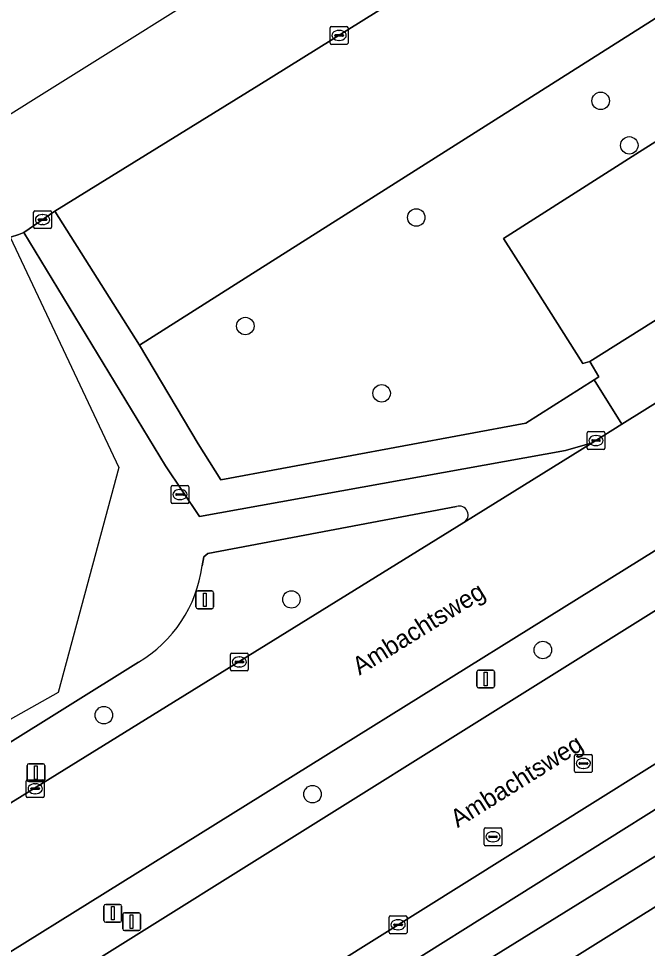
# Model space of a CAD drawing. Extents: x 158455 to 159797, y 387218 to 388672.
# Drawn here: x 158486.5 to 158521.8, y 387842.6 to 387894.7 of the extents above; entities that cross this region are included whole.
import ezdxf

# ---------------------------------------------------------------- set-up
doc = ezdxf.new("R2010")
doc.units = 0
for name, color, linetype in [('IMGEO_Berm_groen', 7, 'Continuous'), ('IMGEO_Boom', 7, 'Continuous'), ('IMGEO_Erf', 7, 'Continuous'), ('IMGEO_Fietspad_open', 7, 'Continuous'), ('IMGEO_Groenvoorziening', 7, 'Continuous'), ('IMGEO_Kolk', 7, 'Continuous'), ('IMGEO_Lichtmast', 7, 'Continuous'), ('IMGEO_Openbare_ruimte_label', 7, 'Continuous'), ('IMGEO_Pand', 7, 'Continuous'), ('IMGEO_Rijbaan_lokaal_gesloten', 7, 'Continuous'), ('IMGEO_Rijbaan_lokaal_open', 7, 'Continuous'), ('IMGEO_Rioolput', 7, 'Continuous'), ('IMGEO_Verkeersbordpaal', 7, 'Continuous'), ('IMGEO_Voetpad_open', 7, 'Continuous')]:
    doc.layers.add(name, color=color, linetype=linetype)

msp = doc.modelspace()

# ---------------------------------------------------------------- linework, layer by layer
at = {"layer": 'IMGEO_Berm_groen'}
for points in [[(158511.066, 387867.368), (158497.138, 387864.732), (158496.915, 387864.542), (158496.826, 387864.039)], [(158475.023, 387843.917), (158511.48, 387866.466)], [(158522.28, 387864.951), (158479.024, 387838.051)], [(158480.509, 387835.487), (158523.75, 387862.509)], [(158493.253, 387858.646), (158473.66, 387846.433)]]:
    msp.add_lwpolyline(points, dxfattribs=at)
for centre, radius, start, end in [((158511.214, 387866.89), 0.5, 302.0715, 107.2369), ((158489.463, 387865.037), 7.431, 300.6705, 352.2785)]:
    msp.add_arc(centre, radius, start, end, dxfattribs=at)
at = {"layer": 'IMGEO_Boom'}
for centre in [(158519.135, 387890.071), (158520.738, 387887.579), (158508.811, 387883.542), (158499.24, 387877.465), (158506.872, 387873.699), (158501.823, 387862.161), (158515.9, 387859.331), (158491.32, 387855.679), (158503.005, 387851.257)]:
    msp.add_circle(centre, 0.489, dxfattribs=at)
at = {"layer": 'IMGEO_Erf'}
msp.add_lwpolyline([(158535.835, 387896.338), (158532.941, 387894.608), (158530.053, 387892.77), (158527.156, 387890.928), (158524.238, 387889.072), (158521.319, 387887.219), (158513.704, 387882.37), (158514.815, 387880.615), (158518.14, 387875.366), (158518.531, 387875.474), (158524.198, 387879.051), (158524.955, 387877.885), (158538.307, 387886.237)], dxfattribs=at)
at = {"layer": 'IMGEO_Fietspad_open'}
for points in [[(158511.48, 387866.466), (158518.654, 387870.921), (158517.16, 387870.5), (158496.679, 387866.801), (158494.767, 387869.64), (158486.831, 387882.706), (158486.558, 387882.594), (158486.101, 387882.446), (158486.082, 387882.442), (158486.082, 387882.442), (158492.168, 387869.555), (158488.76, 387856.956), (158471.29, 387847.126)], [(158496.826, 387864.039), (158496.915, 387864.542), (158497.138, 387864.732), (158511.066, 387867.368)], [(158471.29, 387847.126), (158472.279, 387845.559), (158473.66, 387846.433), (158493.253, 387858.646)]]:
    msp.add_lwpolyline(points, dxfattribs=at)
for centre, radius, start, end in [((158511.214, 387866.89), 0.5, 302.0715, 107.2369), ((158489.463, 387865.037), 7.431, 300.6705, 352.2785)]:
    msp.add_arc(centre, radius, start, end, dxfattribs=at)
at = {"layer": 'IMGEO_Groenvoorziening'}
msp.add_lwpolyline([(158488.574, 387883.891), (158493.308, 387876.386), (158500, 387880.63), (158536.681, 387903.888), (158589.704, 387936.796), (158585.207, 387943.981), (158555.076, 387925.231), (158500, 387890.959)], close=True, dxfattribs=at)
msp.add_lwpolyline([(158536.681, 387903.888), (158500, 387880.63), (158493.308, 387876.386), (158496.607, 387870.873), (158497.879, 387868.851), (158514.948, 387872.022), (158518.78, 387874.449), (158519.038, 387874.618), (158518.531, 387875.474), (158518.14, 387875.366), (158514.815, 387880.615), (158513.704, 387882.37), (158521.319, 387887.219), (158524.238, 387889.072), (158527.156, 387890.928), (158530.053, 387892.77), (158532.941, 387894.608), (158535.835, 387896.338)], dxfattribs=at)
at = {"layer": 'IMGEO_Kolk'}
for p, q in [((158503.991, 387893.31), (158503.991, 387894.162)), ((158504.066, 387894.236), (158504.918, 387894.236)), ((158504.479, 387894.016), (158504.504, 387894.016)), ((158504.992, 387894.162), (158504.992, 387893.31)), ((158504.25, 387893.73), (158504.25, 387893.742)), ((158504.688, 387893.693), (158504.29, 387893.693)), ((158504.293, 387893.779), (158504.691, 387893.779)), ((158504.502, 387893.456), (158504.477, 387893.456)), ((158504.734, 387893.742), (158504.734, 387893.73)), ((158504.918, 387893.236), (158504.066, 387893.236)), ((158487.387, 387882.997), (158487.387, 387883.849)), ((158487.462, 387883.923), (158488.314, 387883.923)), ((158487.646, 387883.417), (158487.646, 387883.429)), ((158487.689, 387883.466), (158488.087, 387883.466)), ((158487.875, 387883.703), (158487.9, 387883.703)), ((158488.13, 387883.429), (158488.13, 387883.417)), ((158488.388, 387883.849), (158488.388, 387882.997)), ((158488.314, 387882.923), (158487.462, 387882.923)), ((158488.084, 387883.38), (158487.686, 387883.38)), ((158487.898, 387883.143), (158487.873, 387883.143)), ((158518.374, 387870.629), (158518.374, 387871.481)), ((158518.449, 387871.555), (158519.301, 387871.555)), ((158519.375, 387871.481), (158519.375, 387870.629)), ((158518.633, 387871.049), (158518.633, 387871.061)), ((158519.071, 387871.012), (158518.673, 387871.012)), ((158518.676, 387871.098), (158519.074, 387871.098)), ((158518.862, 387871.335), (158518.887, 387871.335)), ((158519.117, 387871.061), (158519.117, 387871.049)), ((158519.301, 387870.555), (158518.449, 387870.555)), ((158518.885, 387870.775), (158518.86, 387870.775)), ((158495.083, 387867.606), (158495.083, 387868.458)), ((158495.158, 387868.532), (158496.01, 387868.532)), ((158495.571, 387868.312), (158495.596, 387868.312)), ((158496.084, 387868.458), (158496.084, 387867.606)), ((158495.342, 387868.026), (158495.342, 387868.038)), ((158495.78, 387867.989), (158495.382, 387867.989)), ((158495.385, 387868.075), (158495.783, 387868.075)), ((158495.826, 387868.038), (158495.826, 387868.026)), ((158496.01, 387867.532), (158495.158, 387867.532)), ((158495.594, 387867.752), (158495.569, 387867.752)), ((158498.408, 387858.233), (158498.408, 387859.085)), ((158498.483, 387859.159), (158499.335, 387859.159)), ((158499.409, 387859.085), (158499.409, 387858.233)), ((158498.667, 387858.653), (158498.667, 387858.665)), ((158499.105, 387858.616), (158498.707, 387858.616)), ((158498.71, 387858.702), (158499.108, 387858.702)), ((158498.896, 387858.939), (158498.921, 387858.939)), ((158499.151, 387858.665), (158499.151, 387858.653)), ((158499.335, 387858.159), (158498.483, 387858.159)), ((158498.919, 387858.379), (158498.894, 387858.379)), ((158486.975, 387851.139), (158486.975, 387851.991)), ((158487.05, 387852.065), (158487.902, 387852.065)), ((158487.463, 387851.845), (158487.488, 387851.845)), ((158487.976, 387851.991), (158487.976, 387851.139)), ((158487.234, 387851.559), (158487.234, 387851.571)), ((158487.672, 387851.522), (158487.274, 387851.522)), ((158487.277, 387851.608), (158487.675, 387851.608)), ((158487.486, 387851.285), (158487.461, 387851.285)), ((158487.718, 387851.571), (158487.718, 387851.559)), ((158487.902, 387851.065), (158487.05, 387851.065)), ((158507.294, 387843.521), (158507.294, 387844.373)), ((158507.369, 387844.447), (158508.221, 387844.447)), ((158508.295, 387844.373), (158508.295, 387843.521)), ((158507.553, 387843.941), (158507.553, 387843.953)), ((158507.991, 387843.904), (158507.593, 387843.904)), ((158507.596, 387843.99), (158507.994, 387843.99)), ((158507.782, 387844.227), (158507.807, 387844.227)), ((158508.037, 387843.953), (158508.037, 387843.941)), ((158508.221, 387843.447), (158507.369, 387843.447)), ((158507.805, 387843.667), (158507.78, 387843.667))]:
    msp.add_line(p, q, dxfattribs=at)
for points in [[(158503.991, 387893.31), (158503.991, 387894.162)], [(158504.066, 387894.236), (158504.918, 387894.236)], [(158504.992, 387894.162), (158504.992, 387893.31)], [(158504.918, 387893.236), (158504.066, 387893.236)], [(158487.387, 387882.997), (158487.387, 387883.849)], [(158487.462, 387883.923), (158488.314, 387883.923)], [(158488.388, 387883.849), (158488.388, 387882.997)], [(158488.314, 387882.923), (158487.462, 387882.923)], [(158518.374, 387870.629), (158518.374, 387871.481)], [(158518.449, 387871.555), (158519.301, 387871.555)], [(158519.375, 387871.481), (158519.375, 387870.629)], [(158519.301, 387870.555), (158518.449, 387870.555)], [(158495.083, 387867.606), (158495.083, 387868.458)], [(158495.158, 387868.532), (158496.01, 387868.532)], [(158496.084, 387868.458), (158496.084, 387867.606)], [(158496.01, 387867.532), (158495.158, 387867.532)], [(158498.408, 387858.233), (158498.408, 387859.085)], [(158498.483, 387859.159), (158499.335, 387859.159)], [(158499.409, 387859.085), (158499.409, 387858.233)], [(158499.335, 387858.159), (158498.483, 387858.159)], [(158486.975, 387851.139), (158486.975, 387851.991)], [(158487.05, 387852.065), (158487.902, 387852.065)], [(158487.976, 387851.991), (158487.976, 387851.139)], [(158487.902, 387851.065), (158487.05, 387851.065)], [(158507.294, 387843.521), (158507.294, 387844.373)], [(158507.369, 387844.447), (158508.221, 387844.447)], [(158508.295, 387844.373), (158508.295, 387843.521)], [(158508.221, 387843.447), (158507.369, 387843.447)]]:
    msp.add_lwpolyline(points, dxfattribs=at)
for centre, radius, start, end in [((158504.068, 387894.16), 0.0765, 91.552, 178.448), ((158504.068, 387894.16), 0.0765, 91.552, 178.448), ((158504.916, 387894.16), 0.0765, 1.552, 88.448), ((158504.916, 387894.16), 0.0765, 1.552, 88.448), ((158504.068, 387893.312), 0.0765, 181.552, 268.448), ((158504.068, 387893.312), 0.0765, 181.552, 268.448), ((158504.29, 387893.739), 0.0403, 85.8775, 175.7526), ((158504.287, 387893.729), 0.0366, 178.938, 274.7102), ((158504.691, 387893.736), 0.043, 264.8664, 352.4533), ((158504.695, 387893.741), 0.0386, 1.7309, 96.639), ((158504.916, 387893.312), 0.0765, 271.552, 358.448), ((158504.916, 387893.312), 0.0765, 271.552, 358.448), ((158487.464, 387883.847), 0.0765, 91.552, 178.448), ((158487.464, 387883.847), 0.0765, 91.552, 178.448), ((158487.686, 387883.426), 0.0403, 85.8775, 175.7526), ((158487.683, 387883.416), 0.0366, 178.938, 274.7102), ((158488.087, 387883.423), 0.043, 264.8664, 352.4533), ((158488.091, 387883.428), 0.0386, 1.7309, 96.639), ((158488.312, 387883.847), 0.0765, 1.552, 88.448), ((158488.312, 387883.847), 0.0765, 1.552, 88.448), ((158487.464, 387882.999), 0.0765, 181.552, 268.448), ((158487.464, 387882.999), 0.0765, 181.552, 268.448), ((158488.312, 387882.999), 0.0765, 271.552, 358.448), ((158488.312, 387882.999), 0.0765, 271.552, 358.448), ((158518.451, 387871.479), 0.0765, 91.552, 178.448), ((158518.451, 387871.479), 0.0765, 91.552, 178.448), ((158519.299, 387871.479), 0.0765, 1.552, 88.448), ((158519.299, 387871.479), 0.0765, 1.552, 88.448), ((158518.673, 387871.058), 0.0403, 85.8775, 175.7526), ((158518.67, 387871.048), 0.0366, 178.938, 274.7102), ((158519.074, 387871.055), 0.043, 264.8664, 352.4533), ((158519.078, 387871.06), 0.0386, 1.7309, 96.639), ((158518.451, 387870.631), 0.0765, 181.552, 268.448), ((158518.451, 387870.631), 0.0765, 181.552, 268.448), ((158519.299, 387870.631), 0.0765, 271.552, 358.448), ((158519.299, 387870.631), 0.0765, 271.552, 358.448), ((158495.16, 387868.456), 0.0765, 91.552, 178.448), ((158495.16, 387868.456), 0.0765, 91.552, 178.448), ((158496.008, 387868.456), 0.0765, 1.552, 88.448), ((158496.008, 387868.456), 0.0765, 1.552, 88.448), ((158495.382, 387868.035), 0.0403, 85.8775, 175.7526), ((158495.379, 387868.025), 0.0366, 178.938, 274.7102), ((158495.783, 387868.032), 0.043, 264.8664, 352.4533), ((158495.787, 387868.037), 0.0386, 1.7309, 96.639), ((158495.16, 387867.608), 0.0765, 181.552, 268.448), ((158495.16, 387867.608), 0.0765, 181.552, 268.448), ((158496.008, 387867.608), 0.0765, 271.552, 358.448), ((158496.008, 387867.608), 0.0765, 271.552, 358.448), ((158498.485, 387859.083), 0.0765, 91.552, 178.448), ((158498.485, 387859.083), 0.0765, 91.552, 178.448), ((158499.333, 387859.083), 0.0765, 1.552, 88.448), ((158499.333, 387859.083), 0.0765, 1.552, 88.448), ((158498.707, 387858.662), 0.0403, 85.8775, 175.7526), ((158498.704, 387858.652), 0.0366, 178.938, 274.7102), ((158499.108, 387858.659), 0.043, 264.8664, 352.4533), ((158499.112, 387858.664), 0.0386, 1.7309, 96.639), ((158498.485, 387858.235), 0.0765, 181.552, 268.448), ((158498.485, 387858.235), 0.0765, 181.552, 268.448), ((158499.333, 387858.235), 0.0765, 271.552, 358.448), ((158499.333, 387858.235), 0.0765, 271.552, 358.448), ((158487.052, 387851.989), 0.0765, 91.552, 178.448), ((158487.052, 387851.989), 0.0765, 91.552, 178.448), ((158487.9, 387851.989), 0.0765, 1.552, 88.448), ((158487.9, 387851.989), 0.0765, 1.552, 88.448), ((158487.052, 387851.141), 0.0765, 181.552, 268.448), ((158487.052, 387851.141), 0.0765, 181.552, 268.448), ((158487.274, 387851.568), 0.0403, 85.8775, 175.7526), ((158487.271, 387851.558), 0.0366, 178.938, 274.7102), ((158487.675, 387851.565), 0.043, 264.8664, 352.4533), ((158487.679, 387851.57), 0.0386, 1.7309, 96.639), ((158487.9, 387851.141), 0.0765, 271.552, 358.448), ((158487.9, 387851.141), 0.0765, 271.552, 358.448), ((158507.371, 387844.371), 0.0765, 91.552, 178.448), ((158507.371, 387844.371), 0.0765, 91.552, 178.448), ((158508.219, 387844.371), 0.0765, 1.552, 88.448), ((158508.219, 387844.371), 0.0765, 1.552, 88.448), ((158507.593, 387843.95), 0.0403, 85.8775, 175.7526), ((158507.59, 387843.94), 0.0366, 178.938, 274.7102), ((158507.994, 387843.947), 0.043, 264.8664, 352.4533), ((158507.998, 387843.952), 0.0386, 1.7309, 96.639), ((158507.371, 387843.523), 0.0765, 181.552, 268.448), ((158507.371, 387843.523), 0.0765, 181.552, 268.448), ((158508.219, 387843.523), 0.0765, 271.552, 358.448), ((158508.219, 387843.523), 0.0765, 271.552, 358.448)]:
    msp.add_arc(centre, radius, start, end, dxfattribs=at)
for centre, major_axis, ratio, start_param, end_param in [((158504.478, 387893.736), (-0.387, 0.002), 0.722429, 4.712389, 7.853982), ((158504.503, 387893.736), (-0.39, 0.002), 0.717154, 1.570796, 4.712389), ((158487.874, 387883.423), (-0.387, 0.002), 0.722429, 4.712389, 7.853982), ((158487.899, 387883.423), (-0.39, 0.002), 0.717154, 1.570796, 4.712389), ((158518.861, 387871.055), (-0.387, 0.002), 0.722429, 4.712389, 7.853982), ((158518.886, 387871.055), (-0.39, 0.002), 0.717154, 1.570796, 4.712389), ((158495.57, 387868.032), (-0.387, 0.002), 0.722429, 4.712389, 7.853982), ((158495.595, 387868.032), (-0.39, 0.002), 0.717154, 1.570796, 4.712389), ((158498.895, 387858.659), (-0.387, 0.002), 0.722429, 4.712389, 7.853982), ((158498.92, 387858.659), (-0.39, 0.002), 0.717154, 1.570796, 4.712389), ((158487.462, 387851.565), (-0.387, 0.002), 0.722429, 4.712389, 7.853982), ((158487.487, 387851.565), (-0.39, 0.002), 0.717154, 1.570796, 4.712389), ((158507.781, 387843.947), (-0.387, 0.002), 0.722429, 4.712389, 7.853982), ((158507.806, 387843.947), (-0.39, 0.002), 0.717154, 1.570796, 4.712389)]:
    msp.add_ellipse(centre, major_axis=major_axis, ratio=ratio, start_param=start_param, end_param=end_param, dxfattribs=at)
at = {"layer": 'IMGEO_Lichtmast'}
for p, q in [((158496.574, 387862.638), (158497.364, 387862.638)), ((158497.364, 387862.638), (158496.574, 387862.638)), ((158496.474, 387861.738), (158496.474, 387862.538)), ((158496.474, 387862.538), (158496.474, 387861.738)), ((158497.464, 387862.538), (158497.464, 387861.738)), ((158497.464, 387861.738), (158497.464, 387862.538)), ((158497.364, 387861.638), (158496.574, 387861.638)), ((158496.574, 387861.638), (158497.364, 387861.638)), ((158512.203, 387857.307), (158512.203, 387858.107)), ((158512.203, 387858.107), (158512.203, 387857.307)), ((158512.303, 387858.207), (158513.093, 387858.207)), ((158513.093, 387858.207), (158512.303, 387858.207)), ((158513.193, 387858.107), (158513.193, 387857.307)), ((158513.193, 387857.307), (158513.193, 387858.107)), ((158513.093, 387857.207), (158512.303, 387857.207)), ((158512.303, 387857.207), (158513.093, 387857.207)), ((158491.323, 387844.19), (158491.323, 387844.99)), ((158491.323, 387844.99), (158491.323, 387844.19)), ((158491.423, 387845.09), (158492.213, 387845.09)), ((158492.213, 387845.09), (158491.423, 387845.09)), ((158492.313, 387844.99), (158492.313, 387844.19)), ((158492.313, 387844.19), (158492.313, 387844.99)), ((158492.213, 387844.09), (158491.423, 387844.09)), ((158491.423, 387844.09), (158492.213, 387844.09))]:
    msp.add_line(p, q, dxfattribs=at)
for points in [[(158496.894, 387862.513), (158497.044, 387862.513), (158497.044, 387861.763), (158496.894, 387861.763), (158496.894, 387862.513)], [(158512.623, 387858.082), (158512.773, 387858.082), (158512.773, 387857.332), (158512.623, 387857.332), (158512.623, 387858.082)], [(158491.743, 387844.965), (158491.893, 387844.965), (158491.893, 387844.215), (158491.743, 387844.215), (158491.743, 387844.965)]]:
    msp.add_lwpolyline(points, dxfattribs=at)
for centre, start, end in [((158496.574, 387862.538), 90, 180), ((158496.574, 387862.538), 90, 180), ((158497.364, 387862.538), 0, 90), ((158497.364, 387862.538), 360, 90), ((158496.574, 387861.738), 180, 270), ((158496.574, 387861.738), 180, 270), ((158497.364, 387861.738), 270, 0), ((158497.364, 387861.738), 270, 0), ((158512.303, 387858.107), 90, 180), ((158512.303, 387858.107), 90, 180), ((158513.093, 387858.107), 0, 90), ((158513.093, 387858.107), 360, 90), ((158512.303, 387857.307), 180, 270), ((158512.303, 387857.307), 180, 270), ((158513.093, 387857.307), 270, 0), ((158513.093, 387857.307), 270, 0), ((158491.423, 387844.99), 90, 180), ((158491.423, 387844.99), 90, 180), ((158492.213, 387844.99), 0, 90), ((158492.213, 387844.99), 360, 90), ((158491.423, 387844.19), 180, 270), ((158491.423, 387844.19), 180, 270), ((158492.213, 387844.19), 270, 0), ((158492.213, 387844.19), 270, 0)]:
    msp.add_arc(centre, 0.1, start, end, dxfattribs=at)
at = {"layer": 'IMGEO_Pand'}
msp.add_lwpolyline([(158590.88, 387815.701), (158566.375, 387854.935), (158566.298, 387855.058), (158558.463, 387867.603), (158533.202, 387851.826), (158531.124, 387850.528), (158499.908, 387831.032), (158500, 387830.885), (158507.802, 387818.394), (158509.51, 387815.659), (158509.563, 387815.483), (158512.249, 387806.568), (158519.071, 387800.209), (158520.945, 387797.209), (158523.788, 387788.298), (158530.633, 387781.857), (158540.227, 387766.495), (158543.85, 387768.758), (158598.774, 387803.062), (158591.008, 387815.497)], close=True, dxfattribs=at)
at = {"layer": 'IMGEO_Rijbaan_lokaal_gesloten'}
for points in [[(158539.837, 387884.088), (158527.354, 387876.349), (158520.321, 387871.964), (158518.654, 387870.921), (158511.48, 387866.466), (158475.023, 387843.917), (158479.024, 387838.051), (158522.28, 387864.951)], [(158487.791, 387830.968), (158490.261, 387832.911), (158491.941, 387834.021), (158548.459, 387869.401)], [(158523.75, 387862.509), (158480.509, 387835.487), (158483.221, 387831.039), (158484.87, 387832.045)]]:
    msp.add_lwpolyline(points, dxfattribs=at)
at = {"layer": 'IMGEO_Rijbaan_lokaal_open'}
msp.add_lwpolyline([(158486.082, 387882.442), (158486.082, 387882.442), (158486.101, 387882.446), (158486.558, 387882.594), (158486.831, 387882.706), (158488.574, 387883.891), (158500, 387890.959), (158555.076, 387925.231), (158551.782, 387930.421), (158483.568, 387887.764)], close=True, dxfattribs=at)
at = {"layer": 'IMGEO_Rioolput'}
for p, q in [((158517.669, 387852.553), (158517.669, 387853.405)), ((158517.744, 387853.479), (158518.596, 387853.479)), ((158518.157, 387853.259), (158518.182, 387853.259)), ((158518.67, 387853.405), (158518.67, 387852.553)), ((158517.928, 387852.973), (158517.928, 387852.985)), ((158518.366, 387852.936), (158517.968, 387852.936)), ((158517.971, 387853.022), (158518.369, 387853.022)), ((158518.18, 387852.699), (158518.155, 387852.699)), ((158518.412, 387852.985), (158518.412, 387852.973)), ((158518.596, 387852.479), (158517.744, 387852.479)), ((158512.607, 387848.447), (158512.607, 387849.299)), ((158512.682, 387849.373), (158513.534, 387849.373)), ((158513.095, 387849.153), (158513.12, 387849.153)), ((158513.608, 387849.299), (158513.608, 387848.447)), ((158512.866, 387848.867), (158512.866, 387848.879)), ((158513.304, 387848.83), (158512.906, 387848.83)), ((158512.909, 387848.916), (158513.307, 387848.916)), ((158513.118, 387848.593), (158513.093, 387848.593)), ((158513.35, 387848.879), (158513.35, 387848.867)), ((158513.534, 387848.373), (158512.682, 387848.373))]:
    msp.add_line(p, q, dxfattribs=at)
for points in [[(158517.669, 387852.553), (158517.669, 387853.405)], [(158517.744, 387853.479), (158518.596, 387853.479)], [(158518.67, 387853.405), (158518.67, 387852.553)], [(158518.596, 387852.479), (158517.744, 387852.479)], [(158512.607, 387848.447), (158512.607, 387849.299)], [(158512.682, 387849.373), (158513.534, 387849.373)], [(158513.608, 387849.299), (158513.608, 387848.447)], [(158513.534, 387848.373), (158512.682, 387848.373)]]:
    msp.add_lwpolyline(points, dxfattribs=at)
for centre, radius, start, end in [((158517.746, 387853.403), 0.0765, 91.552, 178.448), ((158517.746, 387853.403), 0.0765, 91.552, 178.448), ((158518.594, 387853.403), 0.0765, 1.552, 88.448), ((158518.594, 387853.403), 0.0765, 1.552, 88.448), ((158517.968, 387852.982), 0.0403, 85.8775, 175.7526), ((158517.965, 387852.972), 0.0366, 178.938, 274.7102), ((158518.369, 387852.979), 0.043, 264.8664, 352.4533), ((158518.373, 387852.984), 0.0386, 1.7309, 96.639), ((158517.746, 387852.555), 0.0765, 181.552, 268.448), ((158517.746, 387852.555), 0.0765, 181.552, 268.448), ((158518.594, 387852.555), 0.0765, 271.552, 358.448), ((158518.594, 387852.555), 0.0765, 271.552, 358.448), ((158512.684, 387849.297), 0.0765, 91.552, 178.448), ((158512.684, 387849.297), 0.0765, 91.552, 178.448), ((158513.532, 387849.297), 0.0765, 1.552, 88.448), ((158513.532, 387849.297), 0.0765, 1.552, 88.448), ((158512.906, 387848.876), 0.0403, 85.8775, 175.7526), ((158512.903, 387848.866), 0.0366, 178.938, 274.7102), ((158513.307, 387848.873), 0.043, 264.8664, 352.4533), ((158513.311, 387848.878), 0.0386, 1.7309, 96.639), ((158512.684, 387848.449), 0.0765, 181.552, 268.448), ((158512.684, 387848.449), 0.0765, 181.552, 268.448), ((158513.532, 387848.449), 0.0765, 271.552, 358.448), ((158513.532, 387848.449), 0.0765, 271.552, 358.448)]:
    msp.add_arc(centre, radius, start, end, dxfattribs=at)
for centre, major_axis, ratio, start_param, end_param in [((158518.156, 387852.979), (-0.387, 0.002), 0.722429, 4.712389, 7.853982), ((158518.181, 387852.979), (-0.39, 0.002), 0.717154, 1.570796, 4.712389), ((158513.094, 387848.873), (-0.387, 0.002), 0.722429, 4.712389, 7.853982), ((158513.119, 387848.873), (-0.39, 0.002), 0.717154, 1.570796, 4.712389)]:
    msp.add_ellipse(centre, major_axis=major_axis, ratio=ratio, start_param=start_param, end_param=end_param, dxfattribs=at)
at = {"layer": 'IMGEO_Verkeersbordpaal'}
for p, q in [((158487.024, 387852.064), (158487.024, 387852.864)), ((158487.024, 387852.864), (158487.024, 387852.064)), ((158487.124, 387852.964), (158487.914, 387852.964)), ((158487.914, 387852.964), (158487.124, 387852.964)), ((158488.014, 387852.864), (158488.014, 387852.064)), ((158488.014, 387852.064), (158488.014, 387852.864)), ((158487.914, 387851.964), (158487.124, 387851.964)), ((158487.124, 387851.964), (158487.914, 387851.964)), ((158492.38, 387843.722), (158492.38, 387844.522)), ((158492.38, 387844.522), (158492.38, 387843.722)), ((158492.48, 387844.622), (158493.27, 387844.622)), ((158493.27, 387844.622), (158492.48, 387844.622)), ((158493.37, 387844.522), (158493.37, 387843.722)), ((158493.37, 387843.722), (158493.37, 387844.522)), ((158493.27, 387843.622), (158492.48, 387843.622)), ((158492.48, 387843.622), (158493.27, 387843.622))]:
    msp.add_line(p, q, dxfattribs=at)
for points in [[(158487.444, 387852.839), (158487.594, 387852.839), (158487.594, 387852.089), (158487.444, 387852.089), (158487.444, 387852.839)], [(158492.8, 387844.497), (158492.95, 387844.497), (158492.95, 387843.747), (158492.8, 387843.747), (158492.8, 387844.497)]]:
    msp.add_lwpolyline(points, dxfattribs=at)
for centre, start, end in [((158487.124, 387852.864), 90, 180), ((158487.124, 387852.864), 90, 180), ((158487.914, 387852.864), 0, 90), ((158487.914, 387852.864), 360, 90), ((158487.124, 387852.064), 180, 270), ((158487.124, 387852.064), 180, 270), ((158487.914, 387852.064), 270, 0), ((158487.914, 387852.064), 270, 0), ((158492.48, 387844.522), 90, 180), ((158492.48, 387844.522), 90, 180), ((158493.27, 387844.522), 0, 90), ((158493.27, 387844.522), 360, 90), ((158492.48, 387843.722), 180, 270), ((158492.48, 387843.722), 180, 270), ((158493.27, 387843.722), 270, 0), ((158493.27, 387843.722), 270, 0)]:
    msp.add_arc(centre, 0.1, start, end, dxfattribs=at)
at = {"layer": 'IMGEO_Voetpad_open'}
for points in [[(158493.308, 387876.386), (158488.574, 387883.891), (158486.831, 387882.706), (158494.767, 387869.64), (158496.679, 387866.801), (158517.16, 387870.5), (158518.654, 387870.921), (158520.321, 387871.964), (158518.78, 387874.449), (158514.948, 387872.022), (158497.879, 387868.851), (158496.607, 387870.873)], [(158519.038, 387874.618), (158518.78, 387874.449), (158520.321, 387871.964), (158527.354, 387876.349), (158524.955, 387877.885), (158524.198, 387879.051), (158518.531, 387875.474)], [(158528.645, 387854.447), (158488.184, 387829.067), (158489.044, 387827.172), (158493.862, 387830.238), (158529.863, 387852.521)], [(158529.863, 387852.521), (158493.862, 387830.238), (158494.797, 387828.77), (158499.486, 387831.645), (158499.908, 387831.032), (158531.124, 387850.528)]]:
    msp.add_lwpolyline(points, close=True, dxfattribs=at)
for points in [[(158549.075, 387868.445), (158548.459, 387869.401), (158491.941, 387834.021), (158490.261, 387832.911), (158487.791, 387830.968)], [(158487.022, 387830.231), (158488.184, 387829.067), (158528.645, 387854.447)]]:
    msp.add_lwpolyline(points, dxfattribs=at)

# ---------------------------------------------------------------- texts
at = {"layer": 'IMGEO_Openbare_ruimte_label'}
for rotation, p in [(31.9265, (158505.635, 387857.891)), (32.0539, (158511.127, 387849.351))]:
    msp.add_text('Ambachtsweg', height=1, rotation=rotation, dxfattribs=at).set_placement(p)

doc.saveas('drawing.dxf')
